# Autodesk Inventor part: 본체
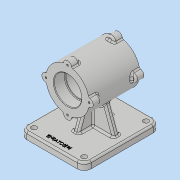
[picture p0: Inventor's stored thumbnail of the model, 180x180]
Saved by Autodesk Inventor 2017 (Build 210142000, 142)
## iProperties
Part Number: 본체
Material: 일반
Document SubType Name: Modeling
Designer: MRC
Density: 1 g/cm^3
Appearance: 기본값
Author: MRC
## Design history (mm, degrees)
sketch "스케치1"
  geometry: L1 (0, 43.5)-(0, 0); L2 (23.5, 43.5)-(37, 43.5); L3 (37, 43.5)-(37, 0); L4 (37, 0)-(21, 0); L5 (23.5, 43.5)-(23.5, 24.5); L6 (23.5, 24.5)-(21, 24.5); L7 (21, 24.5)-(21, 0); 1 further point
  constraints: 14 end point, 4 perpendicular, 2 horizontal alignment, 2 vertical, 1 coincident, 1 horizontal
  dimensions: "d4" = 43.5 distance of L1.start L1.end; "d5" = 47 diameter of L5 L1; "d6" = 42 diameter of L7 L1; "d7" = 19 distance of L2.start L5.end; "d8" = 74 diameter of L3 L1
revolve "회전1" sketch "스케치1" stored, may be unused: angle "d9" = 90 deg
sketch "스케치2"
  geometry: C1 r 23.5 at (0, 0) reference; C2 r 37 at (0, 0) reference; A1 r 7 centre (0, 37) between (6.969, 36.338) and (-6.969, 36.338); A2 r 37 centre (0, 0) between (0, 37) and (-6.969, 36.338) reference; 1 further point
  constraints: 5 point on circle, 1 centre point, 1 vertical alignment
  dimensions: "d10" = 14 diameter of A1
extrude "돌출1" join sketch "스케치2" distance "d11" = 14; taper "d12" = 0 deg
fillet "모깎기1" dims "d13" = 3
hole "구멍1" diameter "d16" = 3.242; stored, may be unused: countersink angle "d20" = 90 deg, drill point angle "d22" = 118 deg; dims "d14" = 10, "d15" = 10, "d17" = 8, "d18" = 4, "d19" = 2, "d21" = 10
chamfer "모따기1" distance "d26" = 1; stored, may be unused: second distance "d27" = 2, angle "d28" = 45 deg
fillet "모깎기2" dims "d29" = 1
sketch "스케치3"
  geometry: L1 (-55, -70)-(55, -70); L2 (55, -70)-(55, -82); L3 (55, -82)-(-55, -82); L4 (-55, -82)-(-55, -70); 2 further points
  constraints: 8 end point, 2 parallel, 1 horizontal, 1 midpoint, 1 perpendicular, 1 vertical alignment
  dimensions: "d30" = 110 distance of L2.end L3.end; "d31" = 82 distance from line of L3 point (0, 0); "d32" = 12 distance of L1.end L2.end
extrude "돌출2" join sketch "스케치3" distance "d33" = 70; taper "d34" = 0 deg; dims "d36" = 60, "d37" = 0
fillet "모깎기3" dims "d35" = 12
sketch "스케치4"
  geometry: L1 (86, 130)-(0, 130) reference; L2 (98, 12)-(98, 118) reference; L3 (0, 0)-(86, 0) reference; L4 (-12, 12)-(-12, 118) reference; C1 r 4.5 at (0, 12); C2 r 4.5 at (86, 12); C3 r 4.5 at (86, 118); C4 r 4.5 at (0, 118); A1 r 12 centre (0, 118) between (0, 130) and (-12, 118) reference; A2 r 12 centre (86, 118) between (98, 118) and (86, 130) reference; A3 r 12 centre (86, 12) between (86, 0) and (98, 12) reference; A4 r 12 centre (0, 12) between (-12, 12) and (0, 0) reference; 1 further point
  constraints: 4 centre point, 4 coincident
  dimensions: "d38" = 9 diameter of C1; "d39" = 9 diameter of C2; "d40" = 9 diameter of C3; "d41" = 9 diameter of C4
extrude "돌출3" cut sketch "스케치4" stored distance "d42" = 0; taper "d43" = 0 deg
sketch "스케치5"
  geometry: L1 (48, 65)-(38, 65); L2 (38, 65)-(38, 75); L3 (38, 75)-(48, 75); L4 (48, 75)-(48, 65); L5 (48, 65)-(38, 75); L6 (38, 65)-(48, 75); 1 further point
  constraints: 12 end point, 2 midpoint, 2 parallel, 1 horizontal, 1 perpendicular
  dimensions: "d44" = 10 distance of L2.end L3.end; "d45" = 10 distance of L1.end L2.end
extrude "돌출4" join sketch "스케치5" stored distance "d46" = 130; taper "d47" = 0 deg
sketch "스케치6"
  geometry: L1 (31.087, -42.765)-(41, -70); L2 (43, -70)-(55, -70) reference; L3 (-43, -70)-(43, -70) reference; L4 (38.5, -70)-(47.5, -70) reference; L5 (-47.5, -70)-(-38.5, -70) reference; L6 (-55, -70)-(-43, -70) reference; L7 (55, -70)-(55, -82) reference; 1 further point
  constraints: 2 end point, 1 point on line
  dimensions: "d48" = 14 distance from line of L7 L1.end; "d49" = 110 deg angle of L2 L1
feature "리브1" sketch "스케치6" dims "d50" = 1, "d51" = 10, "d52" = 0, "d53" = 0, "d54" = 1, "d55" = 1
sketch "스케치7"
  geometry: L1 (-70, -48)-(-70, 58) reference; L2 (-70, 30)-(-48.46, 22.16); 1 further point
  constraints: 2 end point, 1 point on line
  dimensions: "d56" = 110 deg angle of L2 L1; "d57" = 30 vertical distance of point (0, 0) L2.start
feature "리브2" sketch "스케치7" dims "d58" = 1, "d59" = 10, "d60" = 0, "d61" = 0, "d62" = 1, "d63" = 1
fillet "모깎기4" dims "d64" = 3
fillet "모깎기5" dims "d65" = 3
sketch "스케치8"
  geometry: 2 further points
  constraints: 1 vertical alignment, 1 other
  dimensions: "d66" = 58 distance of point (43, -115) point (43, -57)
feature "엠보싱1" sketch "스케치8" dims "d13" = 3, "d67" = 0.5, "d68" = 0
node "솔리드1"
pattern_circular "원형 패턴1" dims angle "d24" = 360 deg
mirror "미러1"
mirror "미러2"
mirror "미러3"
node "투영된 루프1"
node "투영된 루프2"
